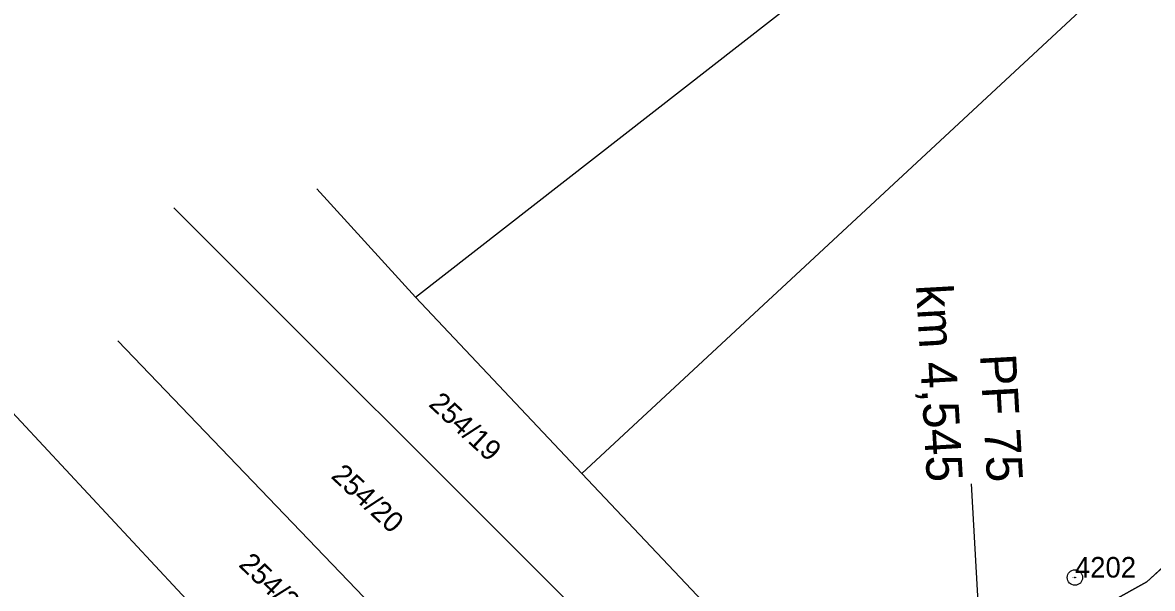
# Model space of a CAD drawing. Extents: x -555757 to -553364, y -1100723 to -1096439.
# Drawn here: x -554288.5 to -554178.6, y -1096808.2 to -1096753.2 of the extents above; entities that cross this region are included whole.
import ezdxf

# ---------------------------------------------------------------- set-up
doc = ezdxf.new("R2010")
doc.units = 0
for name, color, linetype in [('00_NÁVRH - Řezy', 7, 'Continuous'), ('C$SLO$PARCELY', 7, 'Continuous'), ('CISLO_PBPP', 7, 'Continuous'), ('HRANICE$PARCELY', 7, 'Continuous'), ('HRANICE$POROSTU', 7, 'Continuous'), ('OSA$KOLEJI', 7, 'Continuous'), ('SLOUPY', 7, 'Continuous'), ('STROMY', 7, 'Continuous'), ('zájem', 7, 'Continuous')]:
    doc.layers.add(name, color=color, linetype=linetype)

# ---------------------------------------------------------------- blocks, each defined once
blk = doc.blocks.new('1$01')
at = {"layer": 'SLOUPY'}
for radius in [0.75, 0.032]:
    blk.add_circle((0, 0), radius, dxfattribs=at)

msp = doc.modelspace()

# ---------------------------------------------------------------- linework, layer by layer
at = {"layer": '00_NÁVRH - Řezy'}
msp.add_line((-554194.7, -1096825.16), (-554196.22, -1096798.07), dxfattribs=at)
at = {"layer": 'HRANICE$PARCELY'}
for p, q in [((-554250.29, -1096779.93), (-554198.31, -1096739.43)), ((-554250.29, -1096779.93), (-554198.31, -1096739.43)), ((-554234.14, -1096797.06), (-554184.8, -1096751.3)), ((-554234.14, -1096797.06), (-554184.8, -1096751.3)), ((-554259.89, -1096769.42), (-554250.29, -1096779.93)), ((-554259.89, -1096769.42), (-554250.29, -1096779.93)), ((-554273.79, -1096771.25), (-554220.58, -1096824.39)), ((-554273.79, -1096771.25), (-554220.58, -1096824.39)), ((-554250.29, -1096779.93), (-554234.14, -1096797.06)), ((-554250.29, -1096779.93), (-554234.14, -1096797.06)), ((-554279.24, -1096784.17), (-554227.8, -1096837.74)), ((-554279.24, -1096784.17), (-554227.8, -1096837.74)), ((-554290.86, -1096789.71), (-554235.49, -1096849.02)), ((-554290.86, -1096789.71), (-554235.49, -1096849.02)), ((-554234.14, -1096797.06), (-554216.97, -1096815.2)), ((-554234.14, -1096797.06), (-554216.97, -1096815.2))]:
    msp.add_line(p, q, dxfattribs=at)
at = {"layer": 'OSA$KOLEJI'}
for p, q in [((-554142.09, -1096773.54), (-554179.17, -1096807.62)), ((-554142.09, -1096773.54), (-554179.17, -1096807.62)), ((-554179.17, -1096807.62), (-554205.82, -1096822.39)), ((-554179.17, -1096807.62), (-554205.82, -1096822.39))]:
    msp.add_line(p, q, dxfattribs=at)
at = {"layer": 'zájem'}
for points in [[(-554110.69, -1096747.36), (-554142.08, -1096773.53), (-554179.17, -1096807.62), (-554205.78, -1096822.41), (-554208.2, -1096823.7), (-554225.08, -1096837.14), (-554235.5, -1096849), (-554251.97, -1096867.91), (-554264.55, -1096882.42), (-554265.7, -1096883.76), (-554272.88, -1096891.67), (-554281.79, -1096901.5), (-554289.93, -1096910.44), (-554329.92, -1096954.43), (-554333.96, -1096958.92), (-554536.43, -1097182.04), (-554585.15, -1097235.78), (-554588.14, -1097239.01), (-554733.55, -1097399.26)], [(-554733.55, -1097399.26), (-554588.14, -1097239.01), (-554585.15, -1097235.78), (-554536.43, -1097182.04), (-554333.96, -1096958.92), (-554329.92, -1096954.43), (-554289.93, -1096910.44), (-554281.79, -1096901.5), (-554272.88, -1096891.67), (-554265.7, -1096883.76), (-554264.55, -1096882.42), (-554251.97, -1096867.91), (-554235.5, -1096849), (-554225.08, -1096837.14), (-554208.2, -1096823.7), (-554205.78, -1096822.41), (-554179.17, -1096807.62), (-554142.08, -1096773.53), (-554110.69, -1096747.36)]]:
    msp.add_lwpolyline(points, dxfattribs=at)

# ---------------------------------------------------------------- block references
at = {"layer": 'HRANICE$POROSTU'}
msp.add_blockref('1$01', (-554186.18, -1096807.19), dxfattribs=at)

# ---------------------------------------------------------------- texts
at = {"layer": '00_NÁVRH - Řezy'}
for s, p in [('km 4,545', (-554201.64, -1096778.76)), ('PF 75', (-554195.41, -1096785.53))]:
    msp.add_text(s, height=3.5, rotation=273.223, dxfattribs=at).set_placement(p)
at = {"layer": 'C$SLO$PARCELY'}
for s, rotation, p in [('254/19', 317.1025, (-554249.11, -1096790.45)), ('254/20', 317.1025, (-554258.61, -1096797.43)), ('254/21', 316.0025, (-554267.58, -1096806.03))]:
    msp.add_text(s, height=2, rotation=rotation, dxfattribs=at).set_placement(p)
at = {"layer": 'CISLO_PBPP'}
msp.add_text('4202', height=2, dxfattribs=at).set_placement((-554186.18, -1096807.19))
at = {"layer": 'STROMY'}
msp.add_text('246.74', height=0.1, dxfattribs=at).set_placement((-554186.46, -1096807.24))

doc.saveas('drawing.dxf')
